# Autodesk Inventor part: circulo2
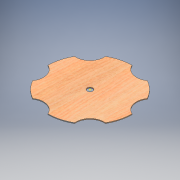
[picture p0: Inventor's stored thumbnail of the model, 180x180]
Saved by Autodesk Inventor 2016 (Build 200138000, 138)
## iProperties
Created: 2016-06
Part Number: circulo2
Material: Genérico
Document SubType Name: Modeling
Designer: adm
Density: 1 g/cm^3
Appearance: Valor por defecto
Author: adm
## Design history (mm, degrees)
sketch "Boceto1"
  geometry: L1 (81.5, 59.5)-(96, 74); L2 (81.5, 59.5)-(60, 81); L3 (96, 74)-(74.5, 95.5); L4 (60, 81)-(74.5, 95.5); L5 (95.045, 116.045)-(95.566, 116.566); L6 (-10.779, 100.331)-(-40.148, 92.462); L7 (-40.148, 92.462)-(-45.455, 112.269); L8 (-10.779, 100.331)-(-16.086, 120.138); L9 (-16.086, 120.138)-(-45.455, 112.269); L10 (-92.279, 40.831)-(-100.148, 11.462); L11 (-100.148, 11.462)-(-119.955, 16.769); L12 (-92.279, 40.831)-(-112.086, 46.138); L13 (-112.086, 46.138)-(-119.955, 16.769); L14 (-81.5, -59.5)-(-60, -81); L15 (-60, -81)-(-74.5, -95.5); L16 (-81.5, -59.5)-(-96, -74); L17 (-96, -74)-(-74.5, -95.5); L18 (10.779, -100.331)-(40.148, -92.462); L19 (40.148, -92.462)-(45.455, -112.269); L20 (10.779, -100.331)-(16.086, -120.138); L21 (16.086, -120.138)-(45.455, -112.269); L22 (92.279, -40.831)-(100.148, -11.462); L23 (100.148, -11.462)-(119.955, -16.769); L24 (92.279, -40.831)-(112.086, -46.138); L25 (112.086, -46.138)-(119.955, -16.769); L26 (-40.148, 92.462)-(-10.779, 100.331); C1 r 10 at (0, 0); A1 r 50 centre (45.655, 170.387) between (0, 150) and (75, 129.904); A2 r 50 centre (-124.732, 124.732) between (-129.904, 75) and (-75, 129.904); A3 r 50 centre (-170.387, -45.655) between (-129.904, -75) and (-150, 0); A4 r 50 centre (-45.655, -170.387) between (0, -150) and (-75, -129.904); A5 r 50 centre (124.732, -124.732) between (129.904, -75) and (75, -129.904); A6 r 50 centre (170.387, 45.655) between (129.904, 75) and (150, 0); A7 r 150 centre (0, 0) between (0, 150) and (-75, 129.904); A8 r 150 centre (0, 0) between (-129.904, 75) and (-150, 0); A9 r 150 centre (0, 0) between (-129.904, -75) and (-75, -129.904); A10 r 150 centre (0, 0) between (0, -150) and (75, -129.904); A11 r 150 centre (0, 0) between (129.904, -75) and (150, 0); A12 r 150 centre (0, 0) between (129.904, 75) and (75, 129.904)
  constraints: 52 end point, 25 point on circle, 13 centre point, 2 equal length, 1 coincident, 74 other
  dimensions: "d4" = 50 radius of A1; "d11" = 360 deg dimension on A7.centre A1.centre (derived); "d15" = 360 deg dimension on A7.centre L1.start (derived); "d17" = 20 diameter of C1
extrude "Extrusión1" new body sketch "Boceto1" distance "d18" = 3; taper "d19" = 0 deg
sketch "Boceto2"
  geometry: L1 (-40.148, 92.462)-(-10.779, 100.331); L2 (-37.56, 82.802)-(-8.19, 90.672); L3 (-10.779, 100.331)-(-8.19, 90.672); L4 (-40.148, 92.462)-(-37.56, 82.802); L5 (-100.148, 11.462)-(-92.279, 40.831); L6 (-100.148, 11.462)-(-90.489, 8.873); L7 (-90.489, 8.873)-(-82.619, 38.243); L8 (-92.279, 40.831)-(-82.619, 38.243); L9 (-60, -81)-(-81.5, -59.5); L10 (-60, -81)-(-52.929, -73.929); L11 (-52.929, -73.929)-(-74.429, -52.429); L12 (-81.5, -59.5)-(-74.429, -52.429); L13 (40.148, -92.462)-(10.779, -100.331); L14 (40.148, -92.462)-(37.56, -82.802); L15 (37.56, -82.802)-(8.19, -90.672); L16 (10.779, -100.331)-(8.19, -90.672); L17 (100.148, -11.462)-(92.279, -40.831); L18 (100.148, -11.462)-(90.489, -8.873); L19 (90.489, -8.873)-(82.619, -38.243); L20 (92.279, -40.831)-(82.619, -38.243); L21 (60, 81)-(81.5, 59.5); L22 (60, 81)-(52.929, 73.929); L23 (52.929, 73.929)-(74.429, 52.429); L24 (81.5, 59.5)-(74.429, 52.429); C1 r 10 at (0, 0) reference; A1 r 150 centre (0, 0) between (129.904, 75) and (75, 129.904) reference; 2 further points
  constraints: 48 end point, 2 parallel, 1 coincident, 49 other
  dimensions: "d23" = 10 distance between parallel lines of L1 L2; "d26" = 360 deg dimension on point (0, 0) L1.start (derived)
extrude "Extrusión2" cut sketch "Boceto2" distance "d28" = 10; taper "d29" = 0 deg
sketch "Boceto3"
  geometry: 1 further point
sketch "Boceto4"
  geometry: L1 (-45.455, 112.269)-(-37.56, 82.802) reference; L2 (-45.455, 112.269)-(-16.086, 120.138); L3 (-16.086, 120.138)-(-8.19, 90.672); L4 (-8.19, 90.672)-(-37.56, 82.802); L5 (-37.56, 82.802)-(-45.455, 112.269); L6 (-119.955, 16.769)-(-112.086, 46.138); L7 (-90.489, 8.873)-(-119.955, 16.769); L8 (-112.086, 46.138)-(-82.619, 38.243); L9 (-82.619, 38.243)-(-90.489, 8.873); L10 (-74.5, -95.5)-(-96, -74); L11 (-52.929, -73.929)-(-74.5, -95.5); L12 (-96, -74)-(-74.429, -52.429); L13 (-74.429, -52.429)-(-52.929, -73.929); L14 (45.455, -112.269)-(16.086, -120.138); L15 (37.56, -82.802)-(45.455, -112.269); L16 (16.086, -120.138)-(8.19, -90.672); L17 (8.19, -90.672)-(37.56, -82.802); L18 (119.955, -16.769)-(112.086, -46.138); L19 (90.489, -8.873)-(119.955, -16.769); L20 (112.086, -46.138)-(82.619, -38.243); L21 (82.619, -38.243)-(90.489, -8.873); L22 (74.5, 95.5)-(96, 74); L23 (52.929, 73.929)-(74.5, 95.5); L24 (96, 74)-(74.429, 52.429); L25 (74.429, 52.429)-(52.929, 73.929); 4 further points
  constraints: 48 end point, 2 perpendicular, 1 coincident, 49 other
  dimensions: "d32" = 360 deg dimension on point (0, 0) L1.start (derived)
extrude "Extrusión3" join sketch "Boceto4" distance "d34" = 3; taper "d35" = 0 deg
node "Sólido1"
other parameters: "d5" = 14.84924
